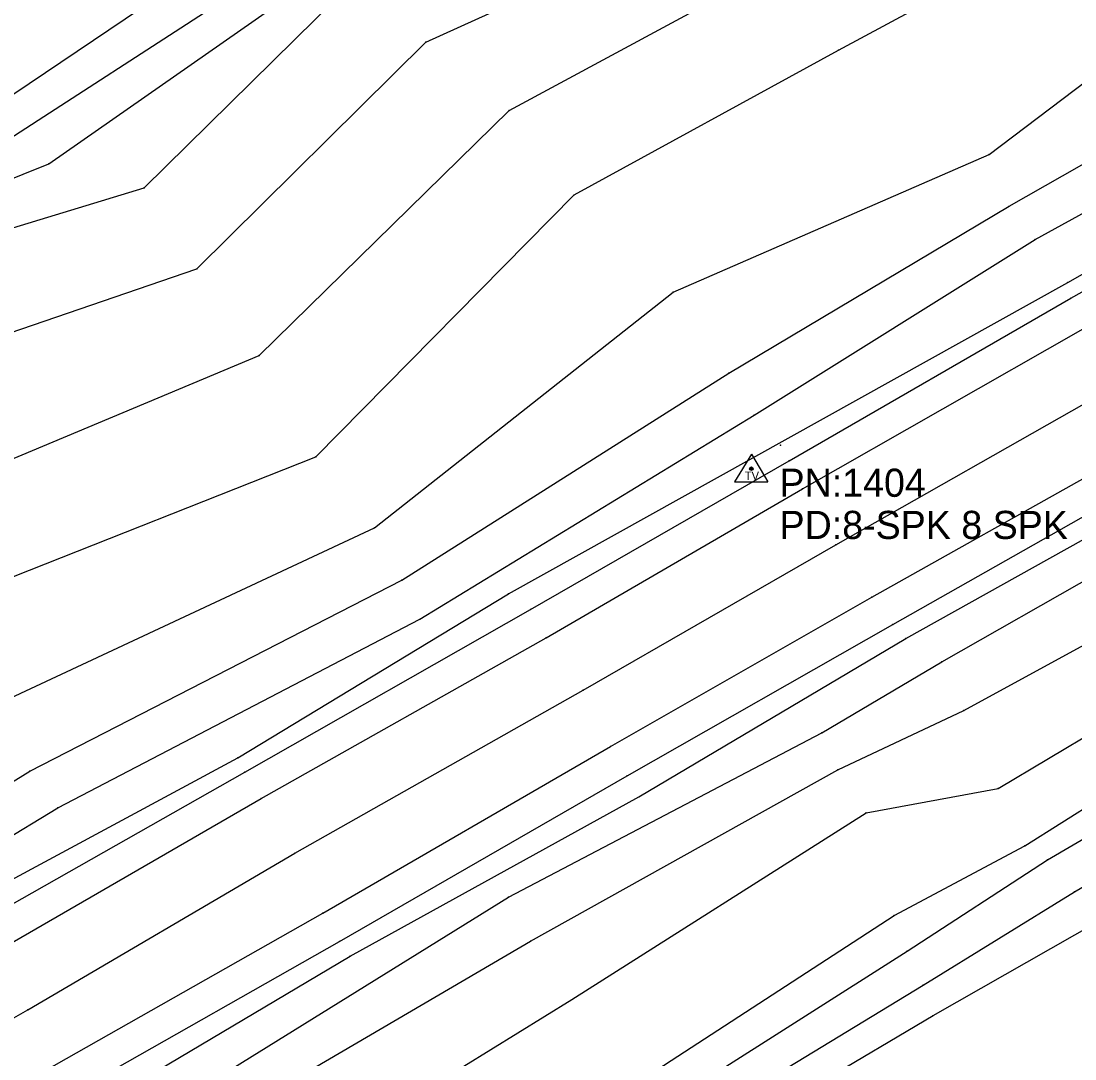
# Model space of a CAD drawing. Extents: x 1419505 to 1434054, y 1956910 to 1968644.
# Drawn here: x 1419862.1 to 1420049.5, y 1957114.6 to 1957299.2 of the extents above; entities that cross this region are included whole.
import ezdxf

# ---------------------------------------------------------------- set-up
doc = ezdxf.new("R2010")
doc.units = 0
for name, color, linetype in [('S_BREAKLINE', 7, 'Continuous'), ('S_DITCHLINE', 7, 'Continuous'), ('S_EDGE_PAVEMENT', 7, 'Continuous'), ('S_GRD_PT_SYM', 7, 'Continuous'), ('S_PAVEMENT_CROWN', 7, 'Continuous'), ('S_RDW_PT_SYM', 7, 'Continuous'), ('S_SECONDARY_CTL', 7, 'Continuous'), ('S_SECONDARY_CTL_ANNOT', 7, 'Continuous'), ('S_SHOULDER', 7, 'Continuous')]:
    doc.layers.add(name, color=color, linetype=linetype)

msp = doc.modelspace()

# ---------------------------------------------------------------- linework, layer by layer
at = {"layer": 'S_BREAKLINE'}
for p, q in [((1419934.1059, 1957295.5182), (1420002.1063, 1957326.3212)), ((1419855.2208, 1957282.5223), (1419910.8484, 1957320.0928)), ((1420007.4567, 1957294.0961), (1420053.3996, 1957318.7217)), ((1419948.9319, 1957283.3594), (1420005.4575, 1957313.8554)), ((1419883.9987, 1957269.5685), (1419922.5522, 1957307.58)), ((1420034.2654, 1957275.5089), (1420062.6502, 1957297.0553)), ((1419893.3483, 1957255.1486), (1419934.1059, 1957295.5182)), ((1419960.5006, 1957268.3374), (1420007.4567, 1957294.0961)), ((1420037.8606, 1957266.3443), (1420070.0887, 1957284.7075)), ((1419904.454, 1957239.7586), (1419948.9319, 1957283.3594)), ((1420048.2403, 1957252.7354), (1420097.7205, 1957280.7592)), ((1420042.4399, 1957260.4189), (1420073.2449, 1957277.283)), ((1419978.0588, 1957251.0513), (1420034.2654, 1957275.5089)), ((1419814.4962, 1957248.4091), (1419883.9987, 1957269.5685)), ((1419914.5497, 1957221.7394), (1419960.5006, 1957268.3374)), ((1419987.9544, 1957236.6354), (1420037.8606, 1957266.3443)), ((1419992.4957, 1957229.1589), (1420042.4399, 1957260.4189)), ((1419827.547, 1957232.6691), (1419893.3483, 1957255.1486)), ((1419948.8149, 1957197.3498), (1420048.2403, 1957252.7354)), ((1419924.9663, 1957209.1056), (1419978.0588, 1957251.0513)), ((1419842.574, 1957213.8119), (1419904.454, 1957239.7586)), ((1419929.8076, 1957199.796), (1419987.9544, 1957236.6354)), ((1419933.0539, 1957192.8816), (1419992.4957, 1957229.1589)), ((1419847.2843, 1957195.1117), (1419914.5497, 1957221.7394)), ((1420019.4294, 1957189.4423), (1420068.6666, 1957216.8621)), ((1419859.2891, 1957178.4016), (1419924.9663, 1957209.1056)), ((1420025.8609, 1957185.2901), (1420063.9153, 1957206.9805)), ((1419863.6694, 1957165.8298), (1419929.8076, 1957199.796)), ((1420029.7541, 1957176.5985), (1420071.8068, 1957199.561)), ((1419900.6558, 1957168.211), (1419948.8149, 1957197.3498)), ((1419868.6507, 1957159.3284), (1419933.0539, 1957192.8816)), ((1419972.0034, 1957161.2345), (1420019.4294, 1957189.4423)), ((1420035.8755, 1957162.7346), (1420081.3434, 1957189.8934)), ((1420004.4905, 1957172.6733), (1420025.8609, 1957185.2901)), ((1420040.6218, 1957152.565), (1420089.794, 1957183.661)), ((1420007.3487, 1957166.0878), (1420029.7541, 1957176.5985)), ((1419948.7939, 1957143.4264), (1420004.4905, 1957172.6733)), ((1419854.5158, 1957143.3884), (1419900.6558, 1957168.211)), ((1419952.6811, 1957135.5669), (1420007.3487, 1957166.0878)), ((1419795.917, 1957124.3391), (1419863.6694, 1957165.8298)), ((1420012.398, 1957158.3993), (1420035.8755, 1957162.7346)), ((1419920.6411, 1957132.9527), (1419972.0034, 1957161.2345)), ((1419799.0002, 1957116.8016), (1419868.6507, 1957159.3284)), ((1419960.0826, 1957125.1932), (1420012.398, 1957158.3993)), ((1420017.4013, 1957140.1762), (1420040.6218, 1957152.565)), ((1419898.0706, 1957111.9563), (1419948.7939, 1957143.4264)), ((1419971.1313, 1957110.1112), (1420017.4013, 1957140.1762)), ((1420024.3448, 1957122.393), (1420053.7557, 1957139.1681)), ((1419900.3037, 1957104.9299), (1419952.6811, 1957135.5669)), ((1419869.3807, 1957102.4977), (1419920.6411, 1957132.9527)), ((1419906.1381, 1957092.025), (1419960.0826, 1957125.1932)), ((1419977.6827, 1957094.7942), (1420024.3448, 1957122.393))]:
    msp.add_line(p, q, dxfattribs=at)
at = {"layer": 'S_DITCHLINE'}
for p, q in [((1419857.289, 1957276.539), (1419916.4178, 1957314.9534)), ((1419867.0476, 1957273.8348), (1419919.773, 1957310.7182)), ((1419815.2753, 1957253.0504), (1419867.0476, 1957273.8348)), ((1420044.6651, 1957150.0788), (1420096.3244, 1957180.3948)), ((1420049.4274, 1957144.3644), (1420104.7479, 1957176.9665)), ((1420019.6995, 1957133.8377), (1420044.6651, 1957150.0788)), ((1420022.5236, 1957127.7864), (1420049.4274, 1957144.3644)), ((1419972.9524, 1957104.0998), (1420019.6995, 1957133.8377)), ((1419975.3036, 1957099.0505), (1420022.5236, 1957127.7864))]:
    msp.add_line(p, q, dxfattribs=at)
at = {"layer": 'S_EDGE_PAVEMENT'}
for p, q in [((1420001.0552, 1957216.0471), (1420051.0225, 1957244.4839)), ((1420013.41, 1957196.7858), (1420063.0773, 1957224.6846)), ((1419955.4793, 1957189.5573), (1420001.0552, 1957216.0471)), ((1419966.922, 1957170.1941), (1420013.41, 1957196.7858)), ((1419904.819, 1957160.9415), (1419955.4793, 1957189.5573)), ((1419915.7587, 1957140.5952), (1419966.922, 1957170.1941)), ((1419859.8281, 1957134.9358), (1419904.819, 1957160.9415)), ((1419866.2125, 1957112.4424), (1419915.7587, 1957140.5952))]:
    msp.add_line(p, q, dxfattribs=at)
at = {"layer": 'S_GRD_PT_SYM'}
for points in [[(1419934.1059, 1957295.5182), (1419934.1059, 1957295.5682), (1419934.1059, 1957295.5182), (1419934.0559, 1957295.5182), (1419934.1059, 1957295.5182), (1419934.1059, 1957295.4682), (1419934.1059, 1957295.5182), (1419934.1559, 1957295.5182)], [(1420007.4567, 1957294.0961), (1420007.4567, 1957294.1461), (1420007.4567, 1957294.0961), (1420007.4067, 1957294.0961), (1420007.4567, 1957294.0961), (1420007.4567, 1957294.0461), (1420007.4567, 1957294.0961), (1420007.5067, 1957294.0961)], [(1419948.9319, 1957283.3594), (1419948.9319, 1957283.4094), (1419948.9319, 1957283.3594), (1419948.8819, 1957283.3594), (1419948.9319, 1957283.3594), (1419948.9319, 1957283.3094), (1419948.9319, 1957283.3594), (1419948.9819, 1957283.3594)], [(1420034.2654, 1957275.5089), (1420034.2654, 1957275.5589), (1420034.2654, 1957275.5089), (1420034.2154, 1957275.5089), (1420034.2654, 1957275.5089), (1420034.2654, 1957275.4589), (1420034.2654, 1957275.5089), (1420034.3154, 1957275.5089)], [(1419867.0476, 1957273.8348), (1419867.0476, 1957273.8848), (1419867.0476, 1957273.8348), (1419866.9976, 1957273.8348), (1419867.0476, 1957273.8348), (1419867.0476, 1957273.7848), (1419867.0476, 1957273.8348), (1419867.0976, 1957273.8348)], [(1419883.9987, 1957269.5685), (1419883.9987, 1957269.6185), (1419883.9987, 1957269.5685), (1419883.9487, 1957269.5685), (1419883.9987, 1957269.5685), (1419883.9987, 1957269.5185), (1419883.9987, 1957269.5685), (1419884.0487, 1957269.5685)], [(1419960.5006, 1957268.3374), (1419960.5006, 1957268.3874), (1419960.5006, 1957268.3374), (1419960.4506, 1957268.3374), (1419960.5006, 1957268.3374), (1419960.5006, 1957268.2874), (1419960.5006, 1957268.3374), (1419960.5506, 1957268.3374)], [(1420037.8606, 1957266.3443), (1420037.8606, 1957266.3943), (1420037.8606, 1957266.3443), (1420037.8106, 1957266.3443), (1420037.8606, 1957266.3443), (1420037.8606, 1957266.2943), (1420037.8606, 1957266.3443), (1420037.9106, 1957266.3443)], [(1420042.4399, 1957260.4189), (1420042.4399, 1957260.4689), (1420042.4399, 1957260.4189), (1420042.3899, 1957260.4189), (1420042.4399, 1957260.4189), (1420042.4399, 1957260.3689), (1420042.4399, 1957260.4189), (1420042.4899, 1957260.4189)], [(1419893.3483, 1957255.1486), (1419893.3483, 1957255.1986), (1419893.3483, 1957255.1486), (1419893.2983, 1957255.1486), (1419893.3483, 1957255.1486), (1419893.3483, 1957255.0986), (1419893.3483, 1957255.1486), (1419893.3983, 1957255.1486)], [(1420048.2403, 1957252.7354), (1420048.2403, 1957252.7854), (1420048.2403, 1957252.7354), (1420048.1903, 1957252.7354), (1420048.2403, 1957252.7354), (1420048.2403, 1957252.6854), (1420048.2403, 1957252.7354), (1420048.2903, 1957252.7354)], [(1419978.0588, 1957251.0513), (1419978.0588, 1957251.1013), (1419978.0588, 1957251.0513), (1419978.0088, 1957251.0513), (1419978.0588, 1957251.0513), (1419978.0588, 1957251.0013), (1419978.0588, 1957251.0513), (1419978.1088, 1957251.0513)], [(1419904.454, 1957239.7586), (1419904.454, 1957239.8086), (1419904.454, 1957239.7586), (1419904.404, 1957239.7586), (1419904.454, 1957239.7586), (1419904.454, 1957239.7086), (1419904.454, 1957239.7586), (1419904.504, 1957239.7586)], [(1419987.9544, 1957236.6354), (1419987.9544, 1957236.6854), (1419987.9544, 1957236.6354), (1419987.9044, 1957236.6354), (1419987.9544, 1957236.6354), (1419987.9544, 1957236.5854), (1419987.9544, 1957236.6354), (1419988.0044, 1957236.6354)], [(1419992.4957, 1957229.1589), (1419992.4957, 1957229.2089), (1419992.4957, 1957229.1589), (1419992.4457, 1957229.1589), (1419992.4957, 1957229.1589), (1419992.4957, 1957229.1089), (1419992.4957, 1957229.1589), (1419992.5457, 1957229.1589)], [(1419997.16, 1957223.8226), (1419997.16, 1957223.8726), (1419997.16, 1957223.8226), (1419997.11, 1957223.8226), (1419997.16, 1957223.8226), (1419997.16, 1957223.7726), (1419997.16, 1957223.8226), (1419997.21, 1957223.8226)], [(1419914.5497, 1957221.7394), (1419914.5497, 1957221.7894), (1419914.5497, 1957221.7394), (1419914.4997, 1957221.7394), (1419914.5497, 1957221.7394), (1419914.5497, 1957221.6894), (1419914.5497, 1957221.7394), (1419914.5997, 1957221.7394)], [(1419924.9663, 1957209.1056), (1419924.9663, 1957209.1556), (1419924.9663, 1957209.1056), (1419924.9163, 1957209.1056), (1419924.9663, 1957209.1056), (1419924.9663, 1957209.0556), (1419924.9663, 1957209.1056), (1419925.0163, 1957209.1056)], [(1419929.8076, 1957199.796), (1419929.8076, 1957199.846), (1419929.8076, 1957199.796), (1419929.7576, 1957199.796), (1419929.8076, 1957199.796), (1419929.8076, 1957199.746), (1419929.8076, 1957199.796), (1419929.8576, 1957199.796)], [(1419948.8149, 1957197.3498), (1419948.8149, 1957197.3998), (1419948.8149, 1957197.3498), (1419948.7649, 1957197.3498), (1419948.8149, 1957197.3498), (1419948.8149, 1957197.2998), (1419948.8149, 1957197.3498), (1419948.8649, 1957197.3498)], [(1419933.0539, 1957192.8816), (1419933.0539, 1957192.9316), (1419933.0539, 1957192.8816), (1419933.0039, 1957192.8816), (1419933.0539, 1957192.8816), (1419933.0539, 1957192.8316), (1419933.0539, 1957192.8816), (1419933.1039, 1957192.8816)], [(1420019.4294, 1957189.4423), (1420019.4294, 1957189.4923), (1420019.4294, 1957189.4423), (1420019.3794, 1957189.4423), (1420019.4294, 1957189.4423), (1420019.4294, 1957189.3923), (1420019.4294, 1957189.4423), (1420019.4794, 1957189.4423)], [(1420025.8609, 1957185.2901), (1420025.8609, 1957185.3401), (1420025.8609, 1957185.2901), (1420025.8109, 1957185.2901), (1420025.8609, 1957185.2901), (1420025.8609, 1957185.2401), (1420025.8609, 1957185.2901), (1420025.9109, 1957185.2901)], [(1420029.7541, 1957176.5985), (1420029.7541, 1957176.6485), (1420029.7541, 1957176.5985), (1420029.7041, 1957176.5985), (1420029.7541, 1957176.5985), (1420029.7541, 1957176.5485), (1420029.7541, 1957176.5985), (1420029.8041, 1957176.5985)], [(1420004.4905, 1957172.6733), (1420004.4905, 1957172.7233), (1420004.4905, 1957172.6733), (1420004.4405, 1957172.6733), (1420004.4905, 1957172.6733), (1420004.4905, 1957172.6233), (1420004.4905, 1957172.6733), (1420004.5405, 1957172.6733)], [(1419900.6558, 1957168.211), (1419900.6558, 1957168.261), (1419900.6558, 1957168.211), (1419900.6058, 1957168.211), (1419900.6558, 1957168.211), (1419900.6558, 1957168.161), (1419900.6558, 1957168.211), (1419900.7058, 1957168.211)], [(1419863.6694, 1957165.8298), (1419863.6694, 1957165.8798), (1419863.6694, 1957165.8298), (1419863.6194, 1957165.8298), (1419863.6694, 1957165.8298), (1419863.6694, 1957165.7798), (1419863.6694, 1957165.8298), (1419863.7194, 1957165.8298)], [(1420007.3487, 1957166.0878), (1420007.3487, 1957166.1378), (1420007.3487, 1957166.0878), (1420007.2987, 1957166.0878), (1420007.3487, 1957166.0878), (1420007.3487, 1957166.0378), (1420007.3487, 1957166.0878), (1420007.3987, 1957166.0878)], [(1420035.8755, 1957162.7346), (1420035.8755, 1957162.7846), (1420035.8755, 1957162.7346), (1420035.8255, 1957162.7346), (1420035.8755, 1957162.7346), (1420035.8755, 1957162.6846), (1420035.8755, 1957162.7346), (1420035.9255, 1957162.7346)], [(1419972.0034, 1957161.2345), (1419972.0034, 1957161.2845), (1419972.0034, 1957161.2345), (1419971.9534, 1957161.2345), (1419972.0034, 1957161.2345), (1419972.0034, 1957161.1845), (1419972.0034, 1957161.2345), (1419972.0534, 1957161.2345)], [(1419868.6507, 1957159.3284), (1419868.6507, 1957159.3784), (1419868.6507, 1957159.3284), (1419868.6007, 1957159.3284), (1419868.6507, 1957159.3284), (1419868.6507, 1957159.2784), (1419868.6507, 1957159.3284), (1419868.7007, 1957159.3284)], [(1420012.398, 1957158.3993), (1420012.398, 1957158.4493), (1420012.398, 1957158.3993), (1420012.348, 1957158.3993), (1420012.398, 1957158.3993), (1420012.398, 1957158.3493), (1420012.398, 1957158.3993), (1420012.448, 1957158.3993)], [(1420040.6218, 1957152.565), (1420040.6218, 1957152.615), (1420040.6218, 1957152.565), (1420040.5718, 1957152.565), (1420040.6218, 1957152.565), (1420040.6218, 1957152.515), (1420040.6218, 1957152.565), (1420040.6718, 1957152.565)], [(1420044.6651, 1957150.0788), (1420044.6651, 1957150.1288), (1420044.6651, 1957150.0788), (1420044.6151, 1957150.0788), (1420044.6651, 1957150.0788), (1420044.6651, 1957150.0288), (1420044.6651, 1957150.0788), (1420044.7151, 1957150.0788)], [(1419948.7939, 1957143.4264), (1419948.7939, 1957143.4764), (1419948.7939, 1957143.4264), (1419948.7439, 1957143.4264), (1419948.7939, 1957143.4264), (1419948.7939, 1957143.3764), (1419948.7939, 1957143.4264), (1419948.8439, 1957143.4264)], [(1420049.4274, 1957144.3644), (1420049.4274, 1957144.4144), (1420049.4274, 1957144.3644), (1420049.3774, 1957144.3644), (1420049.4274, 1957144.3644), (1420049.4274, 1957144.3144), (1420049.4274, 1957144.3644), (1420049.4774, 1957144.3644)], [(1420017.4013, 1957140.1762), (1420017.4013, 1957140.2262), (1420017.4013, 1957140.1762), (1420017.3513, 1957140.1762), (1420017.4013, 1957140.1762), (1420017.4013, 1957140.1262), (1420017.4013, 1957140.1762), (1420017.4513, 1957140.1762)], [(1419952.6811, 1957135.5669), (1419952.6811, 1957135.6169), (1419952.6811, 1957135.5669), (1419952.6311, 1957135.5669), (1419952.6811, 1957135.5669), (1419952.6811, 1957135.5169), (1419952.6811, 1957135.5669), (1419952.7311, 1957135.5669)], [(1419920.6411, 1957132.9527), (1419920.6411, 1957133.0027), (1419920.6411, 1957132.9527), (1419920.5911, 1957132.9527), (1419920.6411, 1957132.9527), (1419920.6411, 1957132.9027), (1419920.6411, 1957132.9527), (1419920.6911, 1957132.9527)], [(1420019.6995, 1957133.8377), (1420019.6995, 1957133.8877), (1420019.6995, 1957133.8377), (1420019.6495, 1957133.8377), (1420019.6995, 1957133.8377), (1420019.6995, 1957133.7877), (1420019.6995, 1957133.8377), (1420019.7495, 1957133.8377)], [(1420022.5236, 1957127.7864), (1420022.5236, 1957127.8364), (1420022.5236, 1957127.7864), (1420022.4736, 1957127.7864), (1420022.5236, 1957127.7864), (1420022.5236, 1957127.7364), (1420022.5236, 1957127.7864), (1420022.5736, 1957127.7864)], [(1419960.0826, 1957125.1932), (1419960.0826, 1957125.2432), (1419960.0826, 1957125.1932), (1419960.0326, 1957125.1932), (1419960.0826, 1957125.1932), (1419960.0826, 1957125.1432), (1419960.0826, 1957125.1932), (1419960.1326, 1957125.1932)], [(1420024.3448, 1957122.393), (1420024.3448, 1957122.443), (1420024.3448, 1957122.393), (1420024.2948, 1957122.393), (1420024.3448, 1957122.393), (1420024.3448, 1957122.343), (1420024.3448, 1957122.393), (1420024.3948, 1957122.393)]]:
    msp.add_lwpolyline(points, dxfattribs=at)
at = {"layer": 'S_PAVEMENT_CROWN'}
for p, q in [((1420007.0106, 1957206.0824), (1420057.8519, 1957235.0013)), ((1419962.0537, 1957180.2207), (1420007.0106, 1957206.0824)), ((1419910.8104, 1957151.2189), (1419962.0537, 1957180.2207)), ((1419863.2824, 1957123.3621), (1419910.8104, 1957151.2189)), ((1419808.6528, 1957092.1611), (1419863.2824, 1957123.3621))]:
    msp.add_line(p, q, dxfattribs=at)
at = {"layer": 'S_RDW_PT_SYM'}
for points in [[(1420048.7923, 1957249.9312), (1420048.7923, 1957249.9812), (1420048.7923, 1957249.9312), (1420048.7423, 1957249.9312), (1420048.7923, 1957249.9312), (1420048.7923, 1957249.8812), (1420048.7923, 1957249.9312), (1420048.8423, 1957249.9312)], [(1419998.7171, 1957221.0414), (1419998.7171, 1957221.0914), (1419998.7171, 1957221.0414), (1419998.6671, 1957221.0414), (1419998.7171, 1957221.0414), (1419998.7171, 1957220.9914), (1419998.7171, 1957221.0414), (1419998.7671, 1957221.0414)], [(1420001.0552, 1957216.0471), (1420001.0552, 1957216.0971), (1420001.0552, 1957216.0471), (1420001.0052, 1957216.0471), (1420001.0552, 1957216.0471), (1420001.0552, 1957215.9971), (1420001.0552, 1957216.0471), (1420001.1052, 1957216.0471)], [(1420007.0106, 1957206.0824), (1420007.0106, 1957206.1324), (1420007.0106, 1957206.0824), (1420006.9606, 1957206.0824), (1420007.0106, 1957206.0824), (1420007.0106, 1957206.0324), (1420007.0106, 1957206.0824), (1420007.0606, 1957206.0824)], [(1420013.41, 1957196.7858), (1420013.41, 1957196.8358), (1420013.41, 1957196.7858), (1420013.36, 1957196.7858), (1420013.41, 1957196.7858), (1420013.41, 1957196.7358), (1420013.41, 1957196.7858), (1420013.46, 1957196.7858)], [(1419952.6931, 1957194.5567), (1419952.6931, 1957194.6067), (1419952.6931, 1957194.5567), (1419952.6431, 1957194.5567), (1419952.6931, 1957194.5567), (1419952.6931, 1957194.5067), (1419952.6931, 1957194.5567), (1419952.7431, 1957194.5567)], [(1420017.1663, 1957191.9195), (1420017.1663, 1957191.9695), (1420017.1663, 1957191.9195), (1420017.1163, 1957191.9195), (1420017.1663, 1957191.9195), (1420017.1663, 1957191.8695), (1420017.1663, 1957191.9195), (1420017.2163, 1957191.9195)], [(1419955.4793, 1957189.5573), (1419955.4793, 1957189.6073), (1419955.4793, 1957189.5573), (1419955.4293, 1957189.5573), (1419955.4793, 1957189.5573), (1419955.4793, 1957189.5073), (1419955.4793, 1957189.5573), (1419955.5293, 1957189.5573)], [(1419962.0537, 1957180.2207), (1419962.0537, 1957180.2707), (1419962.0537, 1957180.2207), (1419962.0037, 1957180.2207), (1419962.0537, 1957180.2207), (1419962.0537, 1957180.1707), (1419962.0537, 1957180.2207), (1419962.1037, 1957180.2207)], [(1419966.922, 1957170.1941), (1419966.922, 1957170.2441), (1419966.922, 1957170.1941), (1419966.872, 1957170.1941), (1419966.922, 1957170.1941), (1419966.922, 1957170.1441), (1419966.922, 1957170.1941), (1419966.972, 1957170.1941)], [(1419901.9028, 1957165.6538), (1419901.9028, 1957165.7038), (1419901.9028, 1957165.6538), (1419901.8528, 1957165.6538), (1419901.9028, 1957165.6538), (1419901.9028, 1957165.6038), (1419901.9028, 1957165.6538), (1419901.9528, 1957165.6538)], [(1419969.8712, 1957165.0138), (1419969.8712, 1957165.0638), (1419969.8712, 1957165.0138), (1419969.8212, 1957165.0138), (1419969.8712, 1957165.0138), (1419969.8712, 1957164.9638), (1419969.8712, 1957165.0138), (1419969.9212, 1957165.0138)], [(1419904.819, 1957160.9415), (1419904.819, 1957160.9915), (1419904.819, 1957160.9415), (1419904.769, 1957160.9415), (1419904.819, 1957160.9415), (1419904.819, 1957160.8915), (1419904.819, 1957160.9415), (1419904.869, 1957160.9415)], [(1419910.8104, 1957151.2189), (1419910.8104, 1957151.2689), (1419910.8104, 1957151.2189), (1419910.7604, 1957151.2189), (1419910.8104, 1957151.2189), (1419910.8104, 1957151.1689), (1419910.8104, 1957151.2189), (1419910.8604, 1957151.2189)], [(1419915.7587, 1957140.5952), (1419915.7587, 1957140.6452), (1419915.7587, 1957140.5952), (1419915.7087, 1957140.5952), (1419915.7587, 1957140.5952), (1419915.7587, 1957140.5452), (1419915.7587, 1957140.5952), (1419915.8087, 1957140.5952)], [(1419918.7119, 1957135.5339), (1419918.7119, 1957135.5839), (1419918.7119, 1957135.5339), (1419918.6619, 1957135.5339), (1419918.7119, 1957135.5339), (1419918.7119, 1957135.4839), (1419918.7119, 1957135.5339), (1419918.7619, 1957135.5339)], [(1419863.2824, 1957123.3621), (1419863.2824, 1957123.4121), (1419863.2824, 1957123.3621), (1419863.2324, 1957123.3621), (1419863.2824, 1957123.3621), (1419863.2824, 1957123.3121), (1419863.2824, 1957123.3621), (1419863.3324, 1957123.3621)]]:
    msp.add_lwpolyline(points, dxfattribs=at)
at = {"layer": 'S_SECONDARY_CTL'}
for p, q in [((1419991.9957, 1957222.2374), (1419988.9857, 1957217.2835)), ((1419991.9957, 1957222.2374), (1419994.943, 1957217.2835)), ((1419988.9857, 1957217.2835), (1419994.943, 1957217.2835))]:
    msp.add_line(p, q, dxfattribs=at)
for radius in [0.3111, 0.1827, 0.1033]:
    msp.add_circle((1419991.9957, 1957219.6273), radius, dxfattribs=at)
at = {"layer": 'S_SHOULDER'}
for p, q in [((1420048.7923, 1957249.9312), (1420098.8566, 1957278.2571)), ((1419998.7171, 1957221.0414), (1420048.7923, 1957249.9312)), ((1419952.6931, 1957194.5567), (1419998.7171, 1957221.0414)), ((1420017.1663, 1957191.9195), (1420066.4545, 1957219.8703)), ((1419901.9028, 1957165.6538), (1419952.6931, 1957194.5567)), ((1419969.8712, 1957165.0138), (1420017.1663, 1957191.9195)), ((1419856.8619, 1957140.1122), (1419901.9028, 1957165.6538)), ((1419918.7119, 1957135.5339), (1419969.8712, 1957165.0138)), ((1419867.7046, 1957106.598), (1419918.7119, 1957135.5339))]:
    msp.add_line(p, q, dxfattribs=at)

# ---------------------------------------------------------------- texts
at = {"layer": 'S_SECONDARY_CTL'}
msp.add_text('TV', height=1.5, rotation=360, dxfattribs=at).set_placement((1419990.791, 1957217.616))
at = {"layer": 'S_SECONDARY_CTL_ANNOT'}
for s, p in [('PN:1404', (1419996.9957, 1957214.6273)), ('PD:8-SPK 8 SPK', (1419996.9957, 1957207.1273))]:
    msp.add_text(s, height=5, dxfattribs=at).set_placement(p)

doc.saveas('drawing.dxf')
